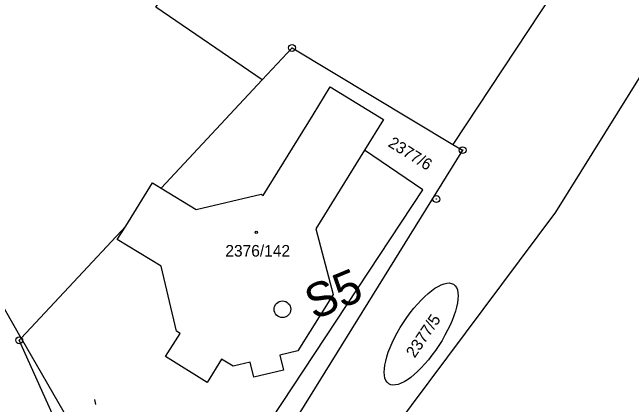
# Model space of a CAD drawing. Extents: x -483721 to -481876, y -1129170 to -1127366.
# Drawn here: x -482229.4 to -482138.7, y -1128184.8 to -1128127.3 of the extents above; entities that cross this region are included whole.
import ezdxf

# ---------------------------------------------------------------- set-up
doc = ezdxf.new("R2010")
doc.units = 0
for name, color, linetype in [('Hranice parcel', 7, 'Continuous'), ('oblast', 7, 'Continuous'), ('Parcelní čísla', 7, 'Continuous'), ('U_IGP', 7, 'Continuous'), ('Značky bodu BP', 7, 'Continuous'), ('Značky budov', 7, 'Continuous'), ('ˇ8', 7, 'Continuous')]:
    doc.layers.add(name, color=color, linetype=linetype)

msp = doc.modelspace()

# ---------------------------------------------------------------- linework, layer by layer
at = {"layer": 'Hranice parcel'}
for p, q in [((-482228.12, -1128175.02), (-482260.19, -1128119.34)), ((-482207.63, -1128153.05), (-482192.81, -1128137.16)), ((-482169.26, -1128153.28), (-482177.8, -1128147.44)), ((-482228.12, -1128175.02), (-482212.81, -1128158.61))]:
    msp.add_line(p, q, dxfattribs=at)
for points in [[(-482192.81, -1128137.16), (-482208.38, -1128126.5), (-482185.6, -1128093.53), (-482171.692, -1128055.235)], [(-482141.078, -1128110.563), (-482164.86, -1128146.61)], [(-482194.8, -1128216.93), (-482149.76, -1128156.56), (-482131.701, -1128127.511)], [(-482192.81, -1128137.16), (-482188.44, -1128132.47), (-482164.86, -1128146.61)], [(-482207.63, -1128153.05), (-482202.5, -1128156.17), (-482192.96, -1128153.9), (-482192.65, -1128154.12), (-482185.36, -1128142.26), (-482182.85, -1128138.16), (-482175.03, -1128142.97), (-482177.8, -1128147.44)], [(-482164.86, -1128146.61), (-482163.44, -1128147.46), (-482202.03, -1128209.75), (-482210.32, -1128212.27)], [(-482177.8, -1128147.44), (-482184.96, -1128159), (-482182.42, -1128168.62), (-482187.61, -1128176.9), (-482190.25, -1128177.51), (-482189.71, -1128179.73), (-482194.04, -1128180.75), (-482194.59, -1128178.57), (-482197.05, -1128179.16), (-482198.77, -1128178.11), (-482200.88, -1128181.52), (-482206.96, -1128177.74), (-482204.85, -1128174.35), (-482205.36, -1128174.03), (-482207.62, -1128164.49), (-482214.05, -1128160.58), (-482212.81, -1128158.61)], [(-482212.81, -1128158.61), (-482208.89, -1128152.23), (-482207.63, -1128153.05)], [(-482228.12, -1128175.02), (-482207.37, -1128211.05), (-482169.26, -1128153.28)], [(-482210.32, -1128212.27), (-482211.62, -1128212.67), (-482228.42, -1128175.35), (-482228.12, -1128175.02)]]:
    msp.add_lwpolyline(points, dxfattribs=at)
at = {"layer": 'oblast'}
msp.add_ellipse((-482169.524, -1128174.427), major_axis=(-4.751, -7.294), ratio=0.355414, dxfattribs=at)
at = {"layer": 'U_IGP'}
msp.add_circle((-482189.848, -1128170.802), 1.223, dxfattribs=at)
at = {"layer": 'Značky bodu BP'}
for centre, radius in [((-482188.44, -1128132.47), 0.5), ((-482188.44, -1128132.47), 0.0303), ((-482163.44, -1128147.46), 0.5), ((-482163.44, -1128147.46), 0.0303), ((-482167.29, -1128154.63), 0.5), ((-482167.29, -1128154.63), 0.0303), ((-482228.42, -1128175.35), 0.5), ((-482228.42, -1128175.35), 0.0303)]:
    msp.add_circle(centre, radius, dxfattribs=at)
at = {"layer": 'Značky budov'}
msp.add_circle((-482193.677, -1128159.529), 0.175, dxfattribs=at)
at = {"layer": 'ˇ8'}
msp.add_line((-482217.398, -1128184.047), (-482217.258, -1128184.767), dxfattribs=at)

# ---------------------------------------------------------------- texts
at = {"layer": 'Parcelní čísla'}
for s, rotation, p in [('2377/6', 328, (-482174.49, -1128146.82)), ('2377/5', 56, (-482170.464, -1128178.034))]:
    msp.add_text(s, height=1.7, rotation=rotation, dxfattribs=at).set_placement(p)
msp.add_text('2376/142', height=1.7, dxfattribs=at).set_placement((-482198.21, -1128163.07))
at = {"layer": 'U_IGP'}
msp.add_text('S5', height=5, rotation=22.52893, dxfattribs=at).set_placement((-482185.223, -1128172.405))

doc.saveas('drawing.dxf')
